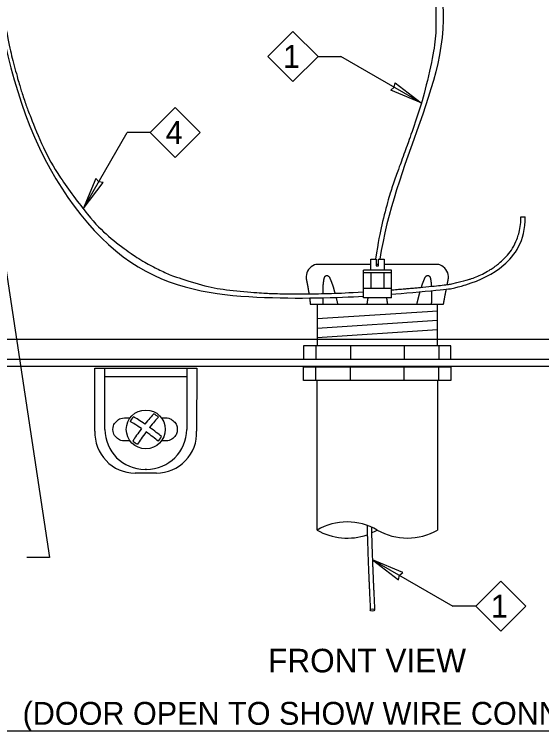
# Model space of a CAD drawing. Extents: x 99862 to 104211, y 98939 to 102076.
# Drawn here: x 101066 to 101435, y 99999 to 100501 of the extents above; entities that cross this region are included whole.
import ezdxf

# ---------------------------------------------------------------- set-up
doc = ezdxf.new("R2010")
doc.units = 0
for name, color, linetype in [('Level 1', 7, 'Continuous'), ('Level 11', 7, 'Continuous'), ('Level 15', 7, 'Continuous'), ('Level 20', 7, 'Continuous'), ('Level 30', 7, 'Continuous'), ('Level 4', 7, 'Continuous'), ('Level 5', 7, 'Continuous'), ('Level 6', 7, 'Continuous'), ('Level 8', 7, 'Continuous'), ('Level 9', 7, 'Continuous')]:
    doc.layers.add(name, color=color, linetype=linetype)

msp = doc.modelspace()

# ---------------------------------------------------------------- linework, layer by layer
at = {"layer": 'Level 1'}
for p, q in [((101638.77, 100273.26), (101021.35, 100273.26)), ((101657.52, 100259.2), (100982.51, 100259.2)), ((101652.84, 100254.51), (100987.19, 100254.51))]:
    msp.add_line(p, q, dxfattribs=at)
msp.add_lwpolyline([(99862, 99999.5), (103151, 99999.5), (103151, 102075.5), (99862, 102075.5)], close=True, dxfattribs=at)
at = {"layer": 'Level 11'}
msp.add_ellipse((101157.93, 100210.36), major_axis=(13.65, 0), ratio=0.995235, dxfattribs=at)
for centre, major_axis, ratio, start_param, end_param in [((101157.93, 100210.65), (-12.13, 0), 0.995235, 5.5003, 5.83226), ((101159.08, 100211.49), (11.69, -8.35), 0.079461, 1.773671, 2.612775), ((101156.5, 100211.11), (-8.77, -11.38), 0.079461, 3.67041, 4.509515), ((101159.66, 100208.67), (8.76, 11.37), 0.079461, 0.529016, 1.356129), ((101157.85, 100210.64), (11.61, 3.51), 0.995235, 0.450926, 0.782886), ((101156.76, 100208.24), (-11.68, 8.35), 0.079461, 4.927057, 5.75417), ((101156.5, 100211.11), (-8.77, -11.38), 0.079461, 4.789717, 5.640927), ((101159.66, 100208.67), (8.76, 11.37), 0.079461, 1.636389, 2.499136), ((101156.76, 100208.24), (-11.68, 8.35), 0.079461, 3.784049, 4.646796), ((101159.08, 100211.49), (11.69, -8.35), 0.079461, 0.642258, 1.493468), ((101157.93, 100210.65), (-12.13, 0), 0.995235, 2.356141, 2.688101), ((101157.85, 100210.64), (11.61, 3.51), 0.995235, 3.595085, 3.927044)]:
    msp.add_ellipse(centre, major_axis=major_axis, ratio=ratio, start_param=start_param, end_param=end_param, dxfattribs=at)
at = {"layer": 'Level 15'}
for p, q in [((101278.5, 100471.42), (101294.5, 100471.42)), ((101350.79, 100438.92), (101294.5, 100471.42)), ((101040.62, 100450.12), (101090.56, 100120.77)), ((101114.12, 100364.82), (101144.91, 100418.15)), ((101160.91, 100418.15), (101144.91, 100418.15)), ((101090.56, 100120.77), (101074.56, 100120.77)), ((101316.62, 100119.11), (101372.91, 100086.61)), ((101388.91, 100086.61), (101372.91, 100086.61))]:
    msp.add_line(p, q, dxfattribs=at)
for points in [[(101350.79, 100438.92), (101329.53, 100447.75), (101331.93, 100449.81), (101332.51, 100452.92)], [(101114.12, 100364.82), (101128.12, 100383.1), (101125.01, 100383.68), (101122.95, 100386.08)], [(101316.62, 100119.11), (101334.89, 100105.11), (101335.47, 100108.23), (101337.88, 100110.28)]]:
    msp.add_lwpolyline(points, close=True, dxfattribs=at)
at = {"layer": 'Level 20'}
for points in [[(101260.94, 100488.97), (101278.5, 100471.42), (101260.94, 100453.87), (101243.39, 100471.42)], [(101178.46, 100435.7), (101196.02, 100418.15), (101178.46, 100400.59), (101160.91, 100418.15)], [(101406.46, 100104.17), (101424.01, 100086.61), (101406.46, 100069.06), (101388.91, 100086.61)]]:
    msp.add_lwpolyline(points, close=True, dxfattribs=at)
at = {"layer": 'Level 30'}
msp.add_line((101420.56, 100359.25), (101423.56, 100359.25), dxfattribs=at)
msp.add_ellipse((101316.62, 100084.02), major_axis=(-1.5, 0), ratio=0.537375, dxfattribs=at)
for points, degree in [([(101269.88, 100591.45), (101282, 100590.84), (101292.57, 100589.02), (101310.95, 100583.5), (101318.77, 100579.8), (101332.08, 100570.97), (101337.57, 100565.84), (101346.63, 100554.55), (101350.2, 100548.39), (101355.72, 100535.44), (101357.68, 100528.64), (101360.29, 100514.87), (101360.95, 100507.92), (101361.26, 100486.84), (101359.26, 100472.48), (101352.44, 100443.15), (101347.61, 100428.17), (101340.86, 100409.08), (101339.48, 100405.24), (101336.66, 100397.53), (101335.23, 100393.65), (101330.91, 100381.52), (101328.02, 100372.78), (101322.93, 100352.99), (101320.69, 100342.29), (101318.76, 100329.44)], 3), ([(101270.03, 100594.45), (101332.31, 100591.28), (101381.05, 100519.79), (101350.57, 100424.68), (101326.88, 100362.98), (101321.79, 100329.44)], 3), ([(101050.83, 100550.12), (101053.01, 100531.91), (101055.8, 100512.03), (101061.94, 100480.78), (101064.55, 100469.36), (101069.14, 100452.77), (101070.79, 100447.34), (101074.32, 100436.74), (101076.22, 100431.58), (101086.28, 100406.47), (101096.21, 100388.64), (101118.68, 100358.15), (101131.21, 100345.5), (101147.75, 100333.34), (101151.1, 100331.09), (101157.89, 100326.95), (101161.32, 100325.06), (101171.72, 100319.88), (101178.81, 100317.06), (101200.44, 100310.21), (101215.37, 100307.75), (101238.15, 100305.83), (101245.81, 100305.48), (101261.19, 100305.15), (101268.91, 100305.16), (101288.28, 100305.5), (101299.75, 100306.02), (101310.29, 100306.65)], 3), ([(101048.01, 100548.43), (101052.16, 100514.02), (101067.9, 100415), (101144.87, 100312.33), (101236.87, 100300.57), (101293.2, 100302.62), (101310.29, 100303.65)], 3), ([(101372.1, 100312.22), (101382.92, 100314.93), (101384.46, 100315.42), (101389.5, 100317.22), (101393.23, 100318.81), (101398.87, 100322.01), (101400.75, 100323.22), (101404.46, 100325.94), (101406.3, 100327.46), (101411.52, 100332.53), (101414.64, 100336.59), (101418.02, 100343.99), (101418.94, 100346.68), (101420.21, 100352.56), (101420.56, 100355.76), (101420.56, 100359.25)], 3), ([(101382.02, 100311.53), (101392.38, 100315.01), (101409.07, 100322.56), (101423.56, 100341.72), (101423.56, 100359.25)], 3), ([(101330.02, 100308.04), (101332.39, 100308.22), (101334.66, 100308.41), (101339.51, 100308.82), (101342.03, 100309.04), (101346.74, 100309.46), (101348.91, 100309.66), (101358.9, 100310.58), (101364.1, 100311.1), (101369.52, 100311.8), (101370.87, 100312.01), (101372.1, 100312.22)], 3), ([(101330.02, 100305.03), (101337.03, 100305.58), (101367.88, 100308.33), (101373.24, 100309.05), (101381.24, 100311.31), (101382.02, 100311.53)], 3), ([(101312.8, 100143.23), (101313.34, 100124.94), (101314.11, 100105.21), (101315.12, 100084.02)], 2), ([(101315.84, 100142.04), (101316.37, 100124.13), (101317.13, 100104.84), (101318.12, 100084.02)], 2)]:
    msp.add_open_spline(points, degree=degree, dxfattribs=at)
at = {"layer": 'Level 4'}
for p, q in [((101277.83, 100297.25), (101277.83, 100268.89)), ((101362.2, 100268.89), (101362.2, 100298.01)), ((101277.83, 100287.92), (101362.38, 100293.44)), ((101277.83, 100281.34), (101362.2, 100286.85)), ((101277.83, 100274.76), (101362.2, 100280.27)), ((101277.05, 100268.89), (101277.05, 100259.52)), ((101301.27, 100268.89), (101301.27, 100259.52)), ((101338.77, 100268.89), (101338.77, 100259.52)), ((101362.98, 100268.89), (101362.98, 100259.52)), ((101277.05, 100244.68), (101277.05, 100254.06)), ((101301.27, 100244.68), (101301.27, 100254.06)), ((101338.77, 100244.68), (101338.77, 100254.06)), ((101362.98, 100244.68), (101362.98, 100254.06)), ((101277.83, 100139.92), (101277.83, 100244.68)), ((101362.2, 100244.68), (101362.2, 100139.92))]:
    msp.add_line(p, q, dxfattribs=at)
for points in [[(101371.58, 100268.89), (101268.45, 100268.89), (101268.45, 100259.52), (101371.58, 100259.52)], [(101371.58, 100244.68), (101268.45, 100244.68), (101268.45, 100254.06), (101371.58, 100254.06)]]:
    msp.add_lwpolyline(points, close=True, dxfattribs=at)
for centre, start, end in [((101298.92, 100103.39), 60, 120), ((101298.92, 100176.46), 240, 289.4959), ((101298.92, 100176.46), 293.8288, 300), ((101341.11, 100176.46), 240, 300)]:
    msp.add_arc(centre, 42.19, start, end, dxfattribs=at)
at = {"layer": 'Level 5'}
for p, q in [((101277.83, 100325.82), (101276.14, 100325.5)), ((101315.4, 100325.82), (101277.83, 100325.82)), ((101320.91, 100325.82), (101319.26, 100325.82)), ((101362.2, 100325.82), (101324.77, 100325.82)), ((101270.16, 100317.35), (101270.17, 100317.4)), ((101270.32, 100315.48), (101270.37, 100315.21)), ((101369.86, 100316.98), (101369.86, 100317.4)), ((101347.74, 100298.01), (101348.6, 100301.55)), ((101273.13, 100298.01), (101347.74, 100298.01)), ((101347.74, 100298.01), (101357.81, 100298.01)), ((101357.81, 100298.01), (101366.35, 100298.01))]:
    msp.add_line(p, q, dxfattribs=at)
for centre, radius, start, end in [((101279.52, 100316.76), 9.38, 111.1568, 176.342), ((101277.83, 100321.13), 4.69, 90, 111.1568), ((101362.2, 100321.13), 4.69, 68.8432, 90), ((101360.51, 100316.76), 9.38, 3.9575, 68.8432)]:
    msp.add_arc(centre, radius, start, end, dxfattribs=at)
for points in [[(101270.17, 100317.4), (101270.12, 100317.47), (101270.2, 100316.6), (101270.32, 100315.48)], [(101270.37, 100315.21), (101270.95, 100312.24), (101271.55, 100309.16), (101272.15, 100305.23)], [(101282.09, 100305.42), (101282.1, 100309.46), (101282.24, 100312.39), (101282.68, 100315.21)], [(101282.68, 100315.21), (101283.08, 100318.09), (101286.32, 100318.08), (101287.15, 100315.21)], [(101287.15, 100315.21), (101288.49, 100312.16), (101289.46, 100308.92), (101290.34, 100305.68)], [(101350.91, 100309.84), (101351.55, 100311.9), (101352.16, 100313.58), (101352.88, 100315.21)], [(101352.88, 100315.21), (101353.72, 100318.09), (101356.96, 100318.08), (101357.35, 100315.21)], [(101357.35, 100315.21), (101357.57, 100313.76), (101357.71, 100312.28), (101357.8, 100310.49)], [(101368.98, 100311.74), (101369.21, 100312.91), (101369.43, 100314.07), (101369.66, 100315.21)], [(101369.66, 100315.21), (101369.76, 100315.99), (101369.83, 100316.6), (101369.86, 100316.98)], [(101348.6, 100301.55), (101349.12, 100303.53), (101349.58, 100305.24), (101350, 100306.75)], [(101357.9, 100307.49), (101357.93, 100306.03), (101357.93, 100304.37), (101357.92, 100302.42)], [(101366.35, 100298.01), (101366.69, 100299.81), (101367.04, 100301.62), (101367.98, 100306.53)], [(101367.98, 100306.53), (101368.11, 100307.23), (101368.25, 100307.93), (101368.38, 100308.63)], [(101272.59, 100302.24), (101272.77, 100300.92), (101272.95, 100299.52), (101273.13, 100298.01)], [(101282.14, 100298.01), (101282.12, 100299.61), (101282.1, 100301.07), (101282.09, 100302.41)], [(101291.14, 100302.7), (101291.17, 100302.61), (101291.19, 100302.51), (101291.22, 100302.42)], [(101291.22, 100302.42), (101291.33, 100301.96), (101291.45, 100301.51), (101292.27, 100298.01)], [(101312.9, 100298.01), (101313.12, 100299.53), (101313.35, 100301.05), (101313.6, 100302.57)], [(101326.4, 100302.57), (101326.65, 100301.05), (101326.88, 100299.52), (101327.13, 100298.01)], [(101357.92, 100302.42), (101357.9, 100300.95), (101357.85, 100299.47), (101357.81, 100298.01)]]:
    msp.add_open_spline(points, degree=2, dxfattribs=at)
at = {"layer": 'Level 6'}
for p, q in [((101122.32, 100209.09), (101122.29, 100253.23)), ((101193.57, 100253.23), (101193.54, 100209.09)), ((101165.45, 100179.84), (101150.42, 100179.84))]:
    msp.add_line(p, q, dxfattribs=at)
for centre, start_param, end_param in [((101150.42, 100207.83), 3.096456, 4.712389), ((101165.45, 100207.83), 4.712389, 6.328322)]:
    msp.add_ellipse(centre, major_axis=(28.12, 0), ratio=0.995235, start_param=start_param, end_param=end_param, dxfattribs=at)
at = {"layer": 'Level 8'}
for p, q in [((101315.4, 100321.94), (101315.4, 100329.44)), ((101315.4, 100329.44), (101319.26, 100329.44)), ((101319.26, 100329.44), (101319.26, 100324.75)), ((101320.91, 100324.75), (101320.91, 100329.44)), ((101320.91, 100329.44), (101324.77, 100329.44)), ((101324.77, 100329.44), (101324.77, 100321.94)), ((101319.26, 100324.75), (101320.91, 100324.75)), ((101330.02, 100321.94), (101310.29, 100321.94)), ((101310.29, 100302.57), (101310.29, 100321.94)), ((101330.02, 100320), (101310.29, 100320)), ((101315.4, 100320), (101315.4, 100309.07)), ((101324.77, 100309.07), (101324.77, 100320)), ((101330.02, 100302.57), (101330.02, 100321.94)), ((101330.02, 100309.07), (101310.29, 100309.07)), ((101330.02, 100302.57), (101310.29, 100302.57))]:
    msp.add_line(p, q, dxfattribs=at)
at = {"layer": 'Level 9'}
for p, q in [((101122.29, 100253.23), (101193.57, 100253.23)), ((101129.29, 100240.96), (101129.29, 100253.23)), ((101186.57, 100253.23), (101186.57, 100240.96)), ((101186.57, 100247.09), (101129.29, 100247.09)), ((101129.29, 100238.33), (101129.29, 100240.96)), ((101186.57, 100240.96), (101186.57, 100238.33)), ((101129.29, 100233.64), (101129.29, 100238.33)), ((101129.29, 100210.36), (101129.29, 100233.64)), ((101186.57, 100238.33), (101186.57, 100233.64)), ((101186.57, 100233.64), (101186.57, 100210.36)), ((101143.02, 100218.37), (101146.91, 100218.37)), ((101168.95, 100218.37), (101171.89, 100218.37)), ((101146.91, 100202.35), (101143.02, 100202.35)), ((101171.89, 100202.35), (101168.95, 100202.35)), ((101158.45, 100182.37), (101157.42, 100182.37))]:
    msp.add_line(p, q, dxfattribs=at)
for centre, start_param, end_param in [((101157.42, 100210.36), 3.141593, 4.712389), ((101158.45, 100210.36), 4.712389, 6.283185)]:
    msp.add_ellipse(centre, major_axis=(28.12, 0), ratio=0.995235, start_param=start_param, end_param=end_param, dxfattribs=at)
for points in [[(101134.94, 100210.36), (101134.94, 100212.48), (101135.79, 100214.51), (101138.81, 100217.52), (101140.87, 100218.37), (101143.02, 100218.37)], [(101171.89, 100218.37), (101171.89, 100218.37), (101171.89, 100218.37), (101174.05, 100218.37), (101176.1, 100217.52), (101179.13, 100214.51), (101179.97, 100212.48), (101179.97, 100208.24), (101179.13, 100206.21), (101176.1, 100203.19), (101174.05, 100202.35), (101171.89, 100202.35)], [(101143.02, 100202.35), (101140.87, 100202.35), (101138.81, 100203.19), (101135.79, 100206.21), (101134.94, 100208.24), (101134.94, 100210.36)]]:
    msp.add_open_spline(points, degree=3, dxfattribs=at)

# ---------------------------------------------------------------- texts
at = {"layer": 'Level 20'}
for s, height, p in [('1', 16, (101253.99, 100463.42)), ('4', 16, (101171.87, 100410.15)), ('1', 16, (101399.51, 100078.62)), ('FRONT VIEW', 16.5, (101243.6, 100040.29)), ('(DOOR OPEN TO SHOW WIRE CONNECTION)', 16, (101071.71, 100003.63))]:
    msp.add_text(s, height=height, dxfattribs=at).set_placement(p)

doc.saveas('drawing.dxf')
